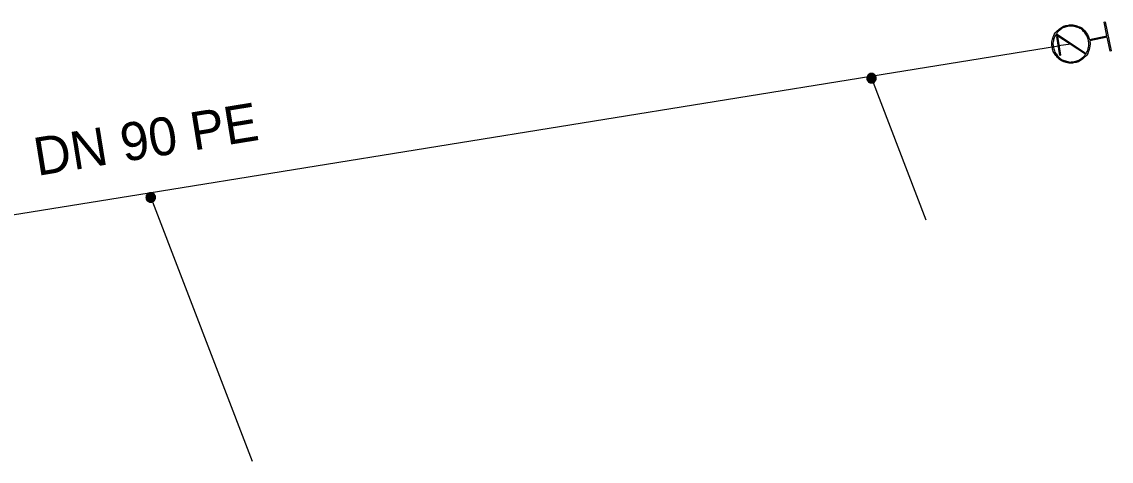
# Model space of a CAD drawing. Extents: x -832382 to -831581, y -1074670 to -1074251.
# Drawn here: x -831683.8 to -831626.5, y -1074411 to -1074387.9 of the extents above; entities that cross this region are included whole.
import ezdxf

# ---------------------------------------------------------------- set-up
doc = ezdxf.new("R2010")
doc.units = 0
for name, color, linetype in [('Hyd-odbočka', 7, 'Continuous'), ('Hyd-šoupě', 7, 'Continuous'), ('Hydrant', 7, 'Continuous'), ('Přípojka vodovodu', 7, 'Continuous'), ('Přípojkový uzávěr', 7, 'Continuous'), ('Roz-řad', 7, 'Continuous'), ('Roz-řad-popis základní', 7, 'Continuous')]:
    doc.layers.add(name, color=color, linetype=linetype)

msp = doc.modelspace()

# ---------------------------------------------------------------- linework, layer by layer
at = {"layer": 'Hyd-odbočka'}
msp.add_line((-831628.62, -1074389.06), (-831629.267, -1074389.162), dxfattribs=at)
at = {"layer": 'Hyd-šoupě'}
msp.add_lwpolyline([(-831629.33, -1074388.666), (-831629.174, -1074389.653), (-831629.204, -1074389.658), (-831629.36, -1074388.671), (-831629.33, -1074388.666)], dxfattribs=at)
at = {"layer": 'Hydrant'}
for points in [[(-831627.647, -1074388.827), (-831626.729, -1074388.638), (-831626.88, -1074387.903), (-831626.819, -1074387.891), (-831626.503, -1074389.421), (-831626.565, -1074389.434), (-831626.716, -1074388.699), (-831627.634, -1074388.889)], [(-831629.388, -1074388.518), (-831627.819, -1074389.551)], [(-831627.852, -1074389.602), (-831629.423, -1074388.57)]]:
    msp.add_lwpolyline(points, dxfattribs=at)
for points in [[(-831627.634, -1074388.889), (-831627.594, -1074389.122), (-831627.667, -1074389.366), (-831627.746, -1074389.625), (-831627.954, -1074389.806), (-831628.162, -1074389.986), (-831628.418, -1074390.039), (-831628.672, -1074390.092), (-831628.932, -1074390.011), (-831629.192, -1074389.93), (-831629.37, -1074389.723), (-831629.547, -1074389.516), (-831629.599, -1074389.262), (-831629.652, -1074389.008), (-831629.571, -1074388.748), (-831629.49, -1074388.488), (-831629.283, -1074388.31), (-831629.076, -1074388.133), (-831628.822, -1074388.081), (-831628.566, -1074388.028), (-831628.303, -1074388.111), (-831628.041, -1074388.195), (-831627.866, -1074388.402), (-831627.703, -1074388.596), (-831627.647, -1074388.827)], [(-831627.819, -1074389.551), (-831627.761, -1074389.455), (-831627.727, -1074389.346), (-831627.654, -1074389.102), (-831627.702, -1074388.871), (-831627.75, -1074388.639), (-831627.914, -1074388.444), (-831628.078, -1074388.248), (-831628.323, -1074388.17), (-831628.568, -1074388.092), (-831628.809, -1074388.142), (-831629.049, -1074388.191), (-831629.241, -1074388.359), (-831629.326, -1074388.43), (-831629.388, -1074388.518)], [(-831629.423, -1074388.57), (-831629.478, -1074388.661), (-831629.51, -1074388.767), (-831629.587, -1074389.01), (-831629.538, -1074389.249), (-831629.489, -1074389.489), (-831629.322, -1074389.682), (-831629.156, -1074389.876), (-831628.913, -1074389.952), (-831628.67, -1074390.027), (-831628.431, -1074389.978), (-831628.19, -1074389.928), (-831627.995, -1074389.759), (-831627.913, -1074389.686), (-831627.852, -1074389.602)]]:
    msp.add_open_spline(points, degree=3, dxfattribs=at)
at = {"layer": 'Přípojka vodovodu'}
for points in [[(-831639.15, -1074390.757), (-831639.11, -1074390.86), (-831636.248, -1074398.307)], [(-831677.099, -1074396.881), (-831677.01, -1074397.13), (-831671.67, -1074411.006)]]:
    msp.add_lwpolyline(points, dxfattribs=at)
at = {"layer": 'Přípojkový uzávěr'}
for points in [[(-831639.11, -1074390.61), (-831639.047, -1074390.61), (-831638.987, -1074390.642), (-831638.928, -1074390.674), (-831638.894, -1074390.735), (-831638.86, -1074390.795), (-831638.86, -1074390.86), (-831638.86, -1074390.925), (-831638.893, -1074390.985), (-831638.926, -1074391.044), (-831638.985, -1074391.077), (-831639.045, -1074391.11), (-831639.11, -1074391.11), (-831639.175, -1074391.11), (-831639.235, -1074391.077), (-831639.294, -1074391.044), (-831639.327, -1074390.985), (-831639.36, -1074390.925), (-831639.36, -1074390.86), (-831639.36, -1074390.795), (-831639.326, -1074390.735), (-831639.293, -1074390.674), (-831639.233, -1074390.642), (-831639.173, -1074390.61), (-831639.11, -1074390.61)], [(-831639.11, -1074390.633), (-831639.167, -1074390.633), (-831639.222, -1074390.663), (-831639.276, -1074390.692), (-831639.306, -1074390.746), (-831639.337, -1074390.801), (-831639.337, -1074390.86), (-831639.337, -1074390.919), (-831639.307, -1074390.973), (-831639.277, -1074391.027), (-831639.223, -1074391.057), (-831639.169, -1074391.087), (-831639.11, -1074391.087), (-831639.051, -1074391.087), (-831638.997, -1074391.057), (-831638.943, -1074391.027), (-831638.913, -1074390.973), (-831638.883, -1074390.919), (-831638.883, -1074390.86), (-831638.883, -1074390.801), (-831638.914, -1074390.746), (-831638.945, -1074390.692), (-831638.999, -1074390.663), (-831639.053, -1074390.633), (-831639.11, -1074390.633)], [(-831639.11, -1074390.651), (-831639.057, -1074390.651), (-831639.007, -1074390.678), (-831638.957, -1074390.704), (-831638.929, -1074390.755), (-831638.901, -1074390.805), (-831638.901, -1074390.86), (-831638.901, -1074390.915), (-831638.928, -1074390.964), (-831638.955, -1074391.014), (-831639.006, -1074391.042), (-831639.056, -1074391.069), (-831639.11, -1074391.069), (-831639.164, -1074391.069), (-831639.214, -1074391.042), (-831639.265, -1074391.014), (-831639.292, -1074390.964), (-831639.319, -1074390.915), (-831639.319, -1074390.86), (-831639.319, -1074390.805), (-831639.291, -1074390.755), (-831639.263, -1074390.704), (-831639.213, -1074390.678), (-831639.163, -1074390.651), (-831639.11, -1074390.651)], [(-831639.11, -1074390.673), (-831639.189, -1074390.673), (-831639.243, -1074390.727), (-831639.297, -1074390.782), (-831639.297, -1074390.86), (-831639.297, -1074390.938), (-831639.243, -1074390.993), (-831639.188, -1074391.048), (-831639.11, -1074391.048), (-831639.032, -1074391.048), (-831638.977, -1074390.993), (-831638.922, -1074390.938), (-831638.922, -1074390.86), (-831638.922, -1074390.782), (-831638.977, -1074390.727), (-831639.032, -1074390.673), (-831639.11, -1074390.673)], [(-831639.11, -1074390.695), (-831639.042, -1074390.695), (-831638.994, -1074390.743), (-831638.946, -1074390.791), (-831638.946, -1074390.86), (-831638.946, -1074390.928), (-831638.994, -1074390.976), (-831639.042, -1074391.024), (-831639.11, -1074391.024), (-831639.179, -1074391.024), (-831639.227, -1074390.976), (-831639.275, -1074390.928), (-831639.275, -1074390.86), (-831639.275, -1074390.791), (-831639.227, -1074390.743), (-831639.179, -1074390.695), (-831639.11, -1074390.695)], [(-831639.11, -1074390.715), (-831639.171, -1074390.715), (-831639.213, -1074390.757), (-831639.255, -1074390.8), (-831639.255, -1074390.86), (-831639.255, -1074390.919), (-831639.213, -1074390.962), (-831639.171, -1074391.004), (-831639.11, -1074391.004), (-831639.051, -1074391.004), (-831639.008, -1074390.962), (-831638.966, -1074390.919), (-831638.966, -1074390.86), (-831638.966, -1074390.8), (-831639.008, -1074390.757), (-831639.05, -1074390.715), (-831639.11, -1074390.715)], [(-831639.11, -1074390.735), (-831639.058, -1074390.735), (-831639.021, -1074390.772), (-831638.985, -1074390.808), (-831638.985, -1074390.86), (-831638.985, -1074390.912), (-831639.022, -1074390.949), (-831639.058, -1074390.985), (-831639.11, -1074390.985), (-831639.162, -1074390.985), (-831639.198, -1074390.949), (-831639.235, -1074390.912), (-831639.235, -1074390.86), (-831639.235, -1074390.808), (-831639.199, -1074390.772), (-831639.162, -1074390.735), (-831639.11, -1074390.735)], [(-831639.11, -1074390.758), (-831639.152, -1074390.758), (-831639.182, -1074390.788), (-831639.212, -1074390.818), (-831639.212, -1074390.86), (-831639.212, -1074390.902), (-831639.182, -1074390.932), (-831639.152, -1074390.961), (-831639.11, -1074390.961), (-831639.068, -1074390.961), (-831639.038, -1074390.932), (-831639.009, -1074390.902), (-831639.009, -1074390.86), (-831639.009, -1074390.818), (-831639.038, -1074390.788), (-831639.068, -1074390.758), (-831639.11, -1074390.758)], [(-831639.11, -1074390.776), (-831639.075, -1074390.776), (-831639.051, -1074390.8), (-831639.026, -1074390.825), (-831639.026, -1074390.86), (-831639.026, -1074390.895), (-831639.051, -1074390.919), (-831639.075, -1074390.944), (-831639.11, -1074390.944), (-831639.145, -1074390.944), (-831639.17, -1074390.919), (-831639.194, -1074390.895), (-831639.194, -1074390.86), (-831639.194, -1074390.825), (-831639.17, -1074390.8), (-831639.145, -1074390.776), (-831639.11, -1074390.776)], [(-831639.11, -1074390.798), (-831639.136, -1074390.798), (-831639.154, -1074390.816), (-831639.172, -1074390.834), (-831639.172, -1074390.86), (-831639.172, -1074390.886), (-831639.154, -1074390.904), (-831639.136, -1074390.923), (-831639.11, -1074390.923), (-831639.084, -1074390.923), (-831639.066, -1074390.904), (-831639.047, -1074390.886), (-831639.047, -1074390.86), (-831639.047, -1074390.834), (-831639.066, -1074390.816), (-831639.084, -1074390.798), (-831639.11, -1074390.798)], [(-831639.11, -1074390.821), (-831639.094, -1074390.821), (-831639.082, -1074390.832), (-831639.071, -1074390.843), (-831639.071, -1074390.86), (-831639.071, -1074390.876), (-831639.082, -1074390.888), (-831639.094, -1074390.899), (-831639.11, -1074390.899), (-831639.126, -1074390.899), (-831639.138, -1074390.888), (-831639.149, -1074390.876), (-831639.149, -1074390.86), (-831639.149, -1074390.843), (-831639.138, -1074390.832), (-831639.126, -1074390.821), (-831639.11, -1074390.821)], [(-831639.11, -1074390.837), (-831639.12, -1074390.837), (-831639.127, -1074390.843), (-831639.134, -1074390.85), (-831639.134, -1074390.86), (-831639.134, -1074390.87), (-831639.127, -1074390.877), (-831639.12, -1074390.883), (-831639.11, -1074390.883), (-831639.1, -1074390.883), (-831639.094, -1074390.877), (-831639.087, -1074390.87), (-831639.087, -1074390.86), (-831639.087, -1074390.85), (-831639.094, -1074390.843), (-831639.1, -1074390.837), (-831639.11, -1074390.837)], [(-831677.01, -1074396.88), (-831676.947, -1074396.88), (-831676.887, -1074396.912), (-831676.828, -1074396.944), (-831676.794, -1074397.005), (-831676.76, -1074397.065), (-831676.76, -1074397.13), (-831676.76, -1074397.195), (-831676.793, -1074397.255), (-831676.826, -1074397.314), (-831676.885, -1074397.347), (-831676.945, -1074397.38), (-831677.01, -1074397.38), (-831677.075, -1074397.38), (-831677.135, -1074397.347), (-831677.194, -1074397.314), (-831677.227, -1074397.255), (-831677.26, -1074397.195), (-831677.26, -1074397.13), (-831677.26, -1074397.065), (-831677.226, -1074397.005), (-831677.193, -1074396.944), (-831677.133, -1074396.912), (-831677.073, -1074396.88), (-831677.01, -1074396.88)], [(-831677.01, -1074396.903), (-831677.067, -1074396.903), (-831677.122, -1074396.933), (-831677.176, -1074396.962), (-831677.206, -1074397.016), (-831677.237, -1074397.071), (-831677.237, -1074397.13), (-831677.237, -1074397.189), (-831677.207, -1074397.243), (-831677.177, -1074397.297), (-831677.123, -1074397.327), (-831677.069, -1074397.357), (-831677.01, -1074397.357), (-831676.951, -1074397.357), (-831676.897, -1074397.327), (-831676.843, -1074397.297), (-831676.813, -1074397.243), (-831676.783, -1074397.189), (-831676.783, -1074397.13), (-831676.783, -1074397.071), (-831676.814, -1074397.016), (-831676.845, -1074396.962), (-831676.899, -1074396.933), (-831676.953, -1074396.903), (-831677.01, -1074396.903)], [(-831677.01, -1074396.921), (-831676.957, -1074396.921), (-831676.907, -1074396.948), (-831676.857, -1074396.974), (-831676.829, -1074397.025), (-831676.801, -1074397.075), (-831676.801, -1074397.13), (-831676.801, -1074397.185), (-831676.828, -1074397.234), (-831676.855, -1074397.284), (-831676.906, -1074397.312), (-831676.956, -1074397.339), (-831677.01, -1074397.339), (-831677.064, -1074397.339), (-831677.114, -1074397.312), (-831677.165, -1074397.284), (-831677.192, -1074397.234), (-831677.219, -1074397.185), (-831677.219, -1074397.13), (-831677.219, -1074397.075), (-831677.191, -1074397.025), (-831677.163, -1074396.974), (-831677.113, -1074396.948), (-831677.063, -1074396.921), (-831677.01, -1074396.921)], [(-831677.01, -1074396.943), (-831677.089, -1074396.943), (-831677.143, -1074396.997), (-831677.198, -1074397.052), (-831677.198, -1074397.13), (-831677.198, -1074397.208), (-831677.143, -1074397.263), (-831677.088, -1074397.318), (-831677.01, -1074397.318), (-831676.932, -1074397.318), (-831676.877, -1074397.263), (-831676.823, -1074397.208), (-831676.823, -1074397.13), (-831676.823, -1074397.052), (-831676.877, -1074396.997), (-831676.932, -1074396.943), (-831677.01, -1074396.943)], [(-831677.01, -1074396.965), (-831676.942, -1074396.965), (-831676.894, -1074397.013), (-831676.846, -1074397.061), (-831676.846, -1074397.13), (-831676.846, -1074397.198), (-831676.894, -1074397.246), (-831676.942, -1074397.294), (-831677.01, -1074397.294), (-831677.079, -1074397.294), (-831677.127, -1074397.246), (-831677.175, -1074397.198), (-831677.175, -1074397.13), (-831677.175, -1074397.061), (-831677.127, -1074397.013), (-831677.079, -1074396.965), (-831677.01, -1074396.965)], [(-831677.01, -1074396.985), (-831677.071, -1074396.985), (-831677.113, -1074397.027), (-831677.155, -1074397.07), (-831677.155, -1074397.13), (-831677.155, -1074397.189), (-831677.113, -1074397.232), (-831677.071, -1074397.274), (-831677.01, -1074397.274), (-831676.951, -1074397.274), (-831676.908, -1074397.232), (-831676.866, -1074397.189), (-831676.866, -1074397.13), (-831676.866, -1074397.07), (-831676.908, -1074397.027), (-831676.95, -1074396.985), (-831677.01, -1074396.985)], [(-831677.01, -1074397.005), (-831676.958, -1074397.005), (-831676.921, -1074397.042), (-831676.885, -1074397.078), (-831676.885, -1074397.13), (-831676.885, -1074397.182), (-831676.922, -1074397.219), (-831676.958, -1074397.255), (-831677.01, -1074397.255), (-831677.062, -1074397.255), (-831677.098, -1074397.219), (-831677.135, -1074397.182), (-831677.135, -1074397.13), (-831677.135, -1074397.078), (-831677.099, -1074397.042), (-831677.062, -1074397.005), (-831677.01, -1074397.005)], [(-831677.01, -1074397.028), (-831677.052, -1074397.028), (-831677.082, -1074397.058), (-831677.112, -1074397.088), (-831677.112, -1074397.13), (-831677.112, -1074397.172), (-831677.082, -1074397.202), (-831677.052, -1074397.231), (-831677.01, -1074397.231), (-831676.968, -1074397.231), (-831676.938, -1074397.202), (-831676.909, -1074397.172), (-831676.909, -1074397.13), (-831676.909, -1074397.088), (-831676.938, -1074397.058), (-831676.968, -1074397.028), (-831677.01, -1074397.028)], [(-831677.01, -1074397.046), (-831676.975, -1074397.046), (-831676.951, -1074397.07), (-831676.926, -1074397.095), (-831676.926, -1074397.13), (-831676.926, -1074397.165), (-831676.951, -1074397.189), (-831676.975, -1074397.214), (-831677.01, -1074397.214), (-831677.045, -1074397.214), (-831677.07, -1074397.189), (-831677.094, -1074397.165), (-831677.094, -1074397.13), (-831677.094, -1074397.095), (-831677.07, -1074397.07), (-831677.045, -1074397.046), (-831677.01, -1074397.046)], [(-831677.01, -1074397.068), (-831677.036, -1074397.068), (-831677.054, -1074397.086), (-831677.073, -1074397.104), (-831677.073, -1074397.13), (-831677.073, -1074397.156), (-831677.054, -1074397.174), (-831677.036, -1074397.193), (-831677.01, -1074397.193), (-831676.984, -1074397.193), (-831676.966, -1074397.174), (-831676.948, -1074397.156), (-831676.948, -1074397.13), (-831676.948, -1074397.104), (-831676.966, -1074397.086), (-831676.984, -1074397.068), (-831677.01, -1074397.068)], [(-831677.01, -1074397.091), (-831676.994, -1074397.091), (-831676.982, -1074397.102), (-831676.971, -1074397.113), (-831676.971, -1074397.13), (-831676.971, -1074397.146), (-831676.982, -1074397.158), (-831676.994, -1074397.169), (-831677.01, -1074397.169), (-831677.026, -1074397.169), (-831677.038, -1074397.158), (-831677.049, -1074397.146), (-831677.049, -1074397.13), (-831677.049, -1074397.113), (-831677.038, -1074397.102), (-831677.026, -1074397.091), (-831677.01, -1074397.091)], [(-831677.01, -1074397.107), (-831677.02, -1074397.107), (-831677.027, -1074397.113), (-831677.034, -1074397.12), (-831677.034, -1074397.13), (-831677.034, -1074397.14), (-831677.027, -1074397.147), (-831677.02, -1074397.153), (-831677.01, -1074397.153), (-831677, -1074397.153), (-831676.994, -1074397.147), (-831676.987, -1074397.14), (-831676.987, -1074397.13), (-831676.987, -1074397.12), (-831676.994, -1074397.113), (-831677, -1074397.107), (-831677.01, -1074397.107)]]:
    msp.add_open_spline(points, degree=3, dxfattribs=at)
at = {"layer": 'Roz-řad'}
msp.add_lwpolyline([(-831710.62, -1074402.29), (-831698.232, -1074400.291), (-831677.099, -1074396.881), (-831639.15, -1074390.757), (-831629.267, -1074389.162)], dxfattribs=at)

# ---------------------------------------------------------------- texts
at = {"layer": 'Roz-řad-popis základní'}
msp.add_text('DN 90 PE', height=2, rotation=9.228, dxfattribs=at).set_placement((-831682.975, -1074396.001))

doc.saveas('drawing.dxf')
